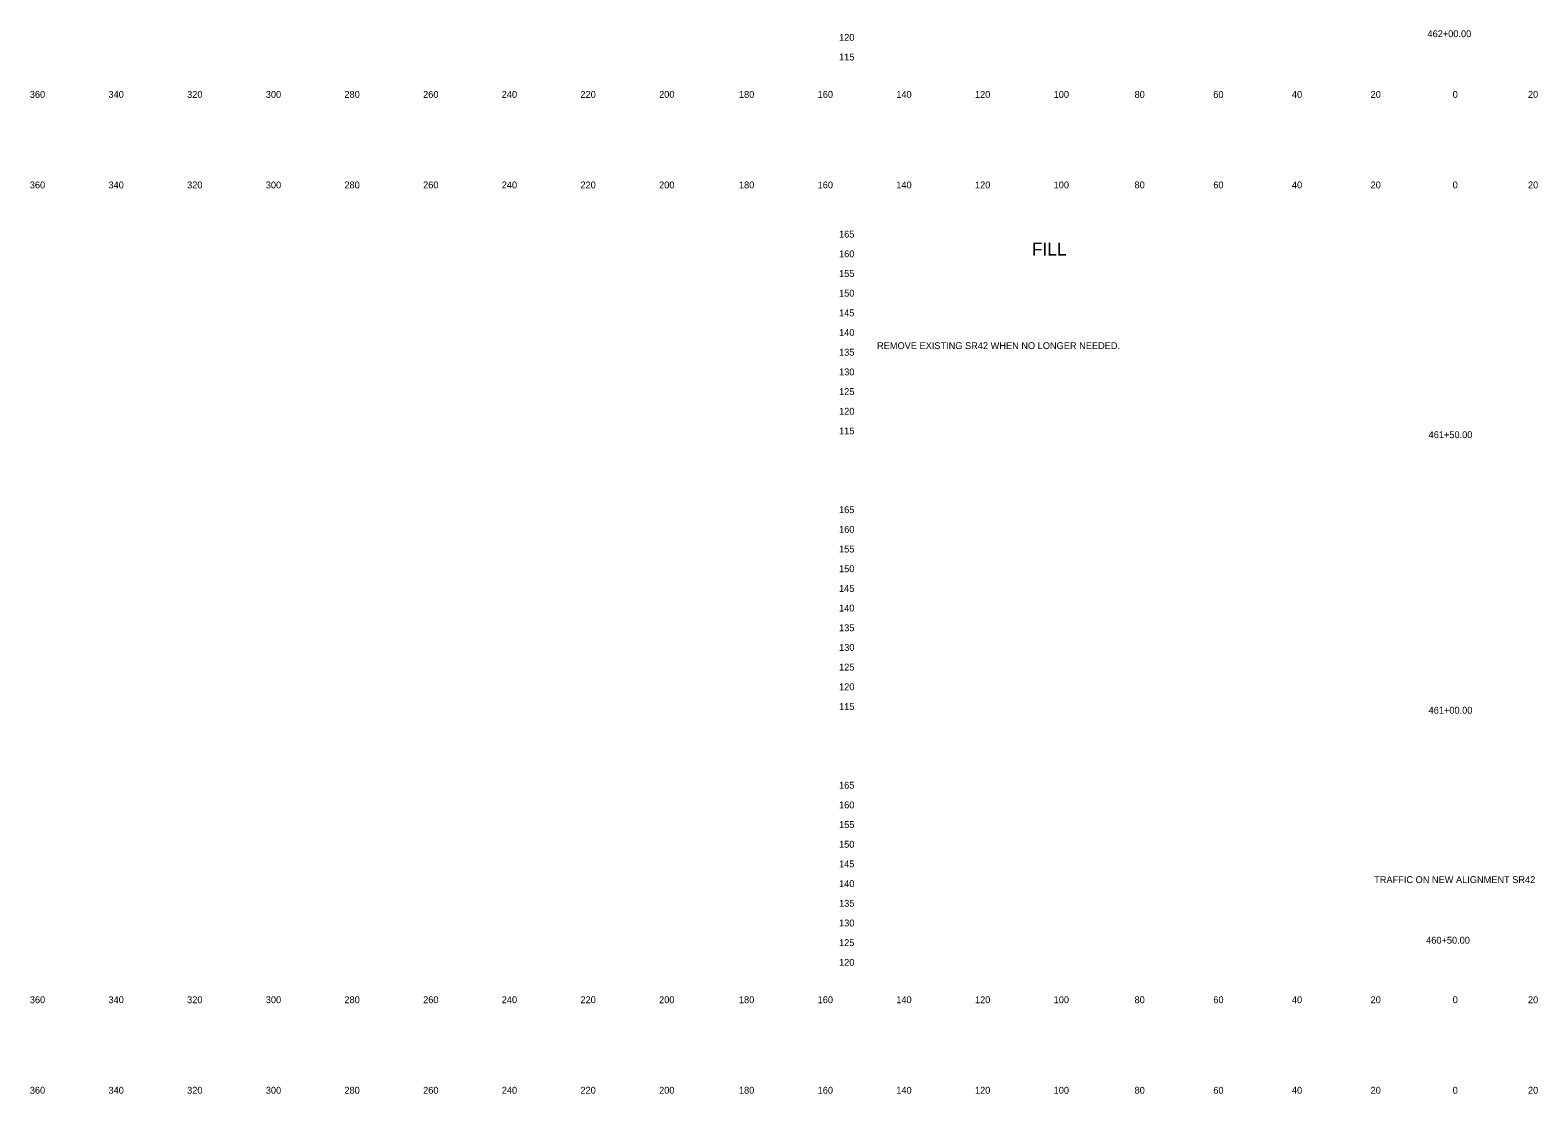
# Model space of a CAD drawing. Extents: x 21281 to 22024, y 6472 to 15208.
# Drawn here: x 21280.5 to 21663.8, y 7832.3 to 8102.5 of the extents above; entities that cross this region are included whole.
import ezdxf

# ---------------------------------------------------------------- set-up
doc = ezdxf.new("R2010")
doc.units = 0
for name, color, linetype in [('XS_SHEET_LABELS_ELEVATION', 7, 'Continuous'), ('XS_SHEET_LABELS_OFFSET', 7, 'Continuous'), ('XS_SHEET_LABELS_STATION', 7, 'Continuous')]:
    doc.layers.add(name, color=color, linetype=linetype)

msp = doc.modelspace()

# ---------------------------------------------------------------- texts
at = {"layer": 'XS_SHEET_LABELS_ELEVATION'}
for s, p in [('  120  ', (21484.84, 8099.84)), ('  115  ', (21484.84, 8094.84)), ('  165  ', (21484.84, 8049.84)), ('  160  ', (21484.84, 8044.84)), ('  155  ', (21484.84, 8039.84)), ('  150  ', (21484.84, 8034.84)), ('  145  ', (21484.84, 8029.84)), ('  140  ', (21484.84, 8024.84)), ('  135  ', (21484.84, 8019.84)), ('  130  ', (21484.84, 8014.84)), ('  125  ', (21484.84, 8009.84)), ('  120  ', (21484.84, 8004.84)), ('  115  ', (21484.84, 7999.84)), ('  165  ', (21484.84, 7979.84)), ('  160  ', (21484.84, 7974.84)), ('  155  ', (21484.84, 7969.84)), ('  150  ', (21484.84, 7964.84)), ('  145  ', (21484.84, 7959.84)), ('  140  ', (21484.84, 7954.84)), ('  135  ', (21484.84, 7949.84)), ('  130  ', (21484.84, 7944.84)), ('  125  ', (21484.84, 7939.84)), ('  120  ', (21484.84, 7934.84)), ('  115  ', (21484.84, 7929.84)), ('  165  ', (21484.84, 7909.84)), ('  160  ', (21484.84, 7904.84)), ('  155  ', (21484.84, 7899.84)), ('  150  ', (21484.84, 7894.84)), ('  145  ', (21484.84, 7889.84)), ('  140  ', (21484.84, 7884.84)), ('  135  ', (21484.84, 7879.84)), ('  130  ', (21484.84, 7874.84)), ('  125  ', (21484.84, 7869.84)), ('  120  ', (21484.84, 7864.84))]:
    msp.add_text(s, height=1.75, dxfattribs=at).set_placement(p)
at = {"layer": 'XS_SHEET_LABELS_OFFSET'}
for s, height, p in [('  360  ', 1.75, (21279.14, 8085.34)), ('  340  ', 1.75, (21299.13, 8085.34)), ('  320  ', 1.75, (21319.13, 8085.34)), ('  300  ', 1.75, (21339.13, 8085.34)), ('  280  ', 1.75, (21359.1, 8085.34)), ('  260  ', 1.75, (21379.11, 8085.34)), ('  240  ', 1.75, (21399.1, 8085.34)), ('  220  ', 1.75, (21419.1, 8085.34)), ('  200  ', 1.75, (21439.1, 8085.34)), ('  180  ', 1.75, (21459.39, 8085.34)), ('  160  ', 1.75, (21479.4, 8085.34)), ('  140  ', 1.75, (21499.39, 8085.34)), ('  120  ', 1.75, (21519.39, 8085.34)), ('  100  ', 1.75, (21539.39, 8085.34)), ('  80  ', 1.75, (21559.95, 8085.34)), ('  60  ', 1.75, (21579.97, 8085.34)), ('  40  ', 1.75, (21599.95, 8085.34)), ('  20  ', 1.75, (21619.95, 8085.34)), ('  0  ', 1.75, (21640.81, 8085.34)), ('  0  ', 1.75, (21640.81, 8085.34)), ('  20  ', 1.75, (21659.95, 8085.34)), ('  360  ', 1.75, (21279.14, 8062.34)), ('  340  ', 1.75, (21299.13, 8062.34)), ('  320  ', 1.75, (21319.13, 8062.34)), ('  300  ', 1.75, (21339.13, 8062.34)), ('  280  ', 1.75, (21359.1, 8062.34)), ('  260  ', 1.75, (21379.11, 8062.34)), ('  240  ', 1.75, (21399.1, 8062.34)), ('  220  ', 1.75, (21419.1, 8062.34)), ('  200  ', 1.75, (21439.1, 8062.34)), ('  180  ', 1.75, (21459.39, 8062.34)), ('  160  ', 1.75, (21479.4, 8062.34)), ('  140  ', 1.75, (21499.39, 8062.34)), ('  120  ', 1.75, (21519.39, 8062.34)), ('  100  ', 1.75, (21539.39, 8062.34)), ('  80  ', 1.75, (21559.95, 8062.34)), ('  60  ', 1.75, (21579.97, 8062.34)), ('  40  ', 1.75, (21599.95, 8062.34)), ('  20  ', 1.75, (21619.95, 8062.34)), ('  0  ', 1.75, (21640.81, 8062.34)), ('  0  ', 1.75, (21640.81, 8062.34)), ('  20  ', 1.75, (21659.95, 8062.34)), ('FILL', 3.273, (21535.18, 8045.29)), ('  360  ', 1.75, (21279.14, 7855.34)), ('  340  ', 1.75, (21299.13, 7855.34)), ('  320  ', 1.75, (21319.13, 7855.34)), ('  300  ', 1.75, (21339.13, 7855.34)), ('  280  ', 1.75, (21359.1, 7855.34)), ('  260  ', 1.75, (21379.11, 7855.34)), ('  240  ', 1.75, (21399.1, 7855.34)), ('  220  ', 1.75, (21419.1, 7855.34)), ('  200  ', 1.75, (21439.1, 7855.34)), ('  180  ', 1.75, (21459.39, 7855.34)), ('  160  ', 1.75, (21479.4, 7855.34)), ('  140  ', 1.75, (21499.39, 7855.34)), ('  120  ', 1.75, (21519.39, 7855.34)), ('  100  ', 1.75, (21539.39, 7855.34)), ('  80  ', 1.75, (21559.95, 7855.34)), ('  60  ', 1.75, (21579.97, 7855.34)), ('  40  ', 1.75, (21599.95, 7855.34)), ('  20  ', 1.75, (21619.95, 7855.34)), ('  0  ', 1.75, (21640.81, 7855.34)), ('  0  ', 1.75, (21640.81, 7855.34)), ('  20  ', 1.75, (21659.95, 7855.34)), ('  360  ', 1.75, (21279.14, 7832.34)), ('  340  ', 1.75, (21299.13, 7832.34)), ('  320  ', 1.75, (21319.13, 7832.34)), ('  300  ', 1.75, (21339.13, 7832.34)), ('  280  ', 1.75, (21359.1, 7832.34)), ('  260  ', 1.75, (21379.11, 7832.34)), ('  240  ', 1.75, (21399.1, 7832.34)), ('  220  ', 1.75, (21419.1, 7832.34)), ('  200  ', 1.75, (21439.1, 7832.34)), ('  180  ', 1.75, (21459.39, 7832.34)), ('  160  ', 1.75, (21479.4, 7832.34)), ('  140  ', 1.75, (21499.39, 7832.34)), ('  120  ', 1.75, (21519.39, 7832.34)), ('  100  ', 1.75, (21539.39, 7832.34)), ('  80  ', 1.75, (21559.95, 7832.34)), ('  60  ', 1.75, (21579.97, 7832.34)), ('  40  ', 1.75, (21599.95, 7832.34)), ('  20  ', 1.75, (21619.95, 7832.34)), ('  0  ', 1.75, (21640.81, 7832.34)), ('  0  ', 1.75, (21640.81, 7832.34)), ('  20  ', 1.75, (21659.95, 7832.34))]:
    msp.add_text(s, height=height, dxfattribs=at).set_placement(p)
at = {"layer": 'XS_SHEET_LABELS_STATION'}
for s, p in [('  462+00.00  ', (21634.41, 8100.76)), ('REMOVE EXISTING SR42 WHEN NO LONGER NEEDED.', (21495.8, 8021.51)), ('  461+50.00  ', (21634.7, 7998.89)), ('  461+00.00  ', (21634.7, 7928.89)), ('TRAFFIC ON NEW ALIGNMENT SR42', (21622.16, 7885.85)), ('  460+50.00  ', (21634.07, 7870.46))]:
    msp.add_text(s, height=1.75, dxfattribs=at).set_placement(p)

doc.saveas('drawing.dxf')
